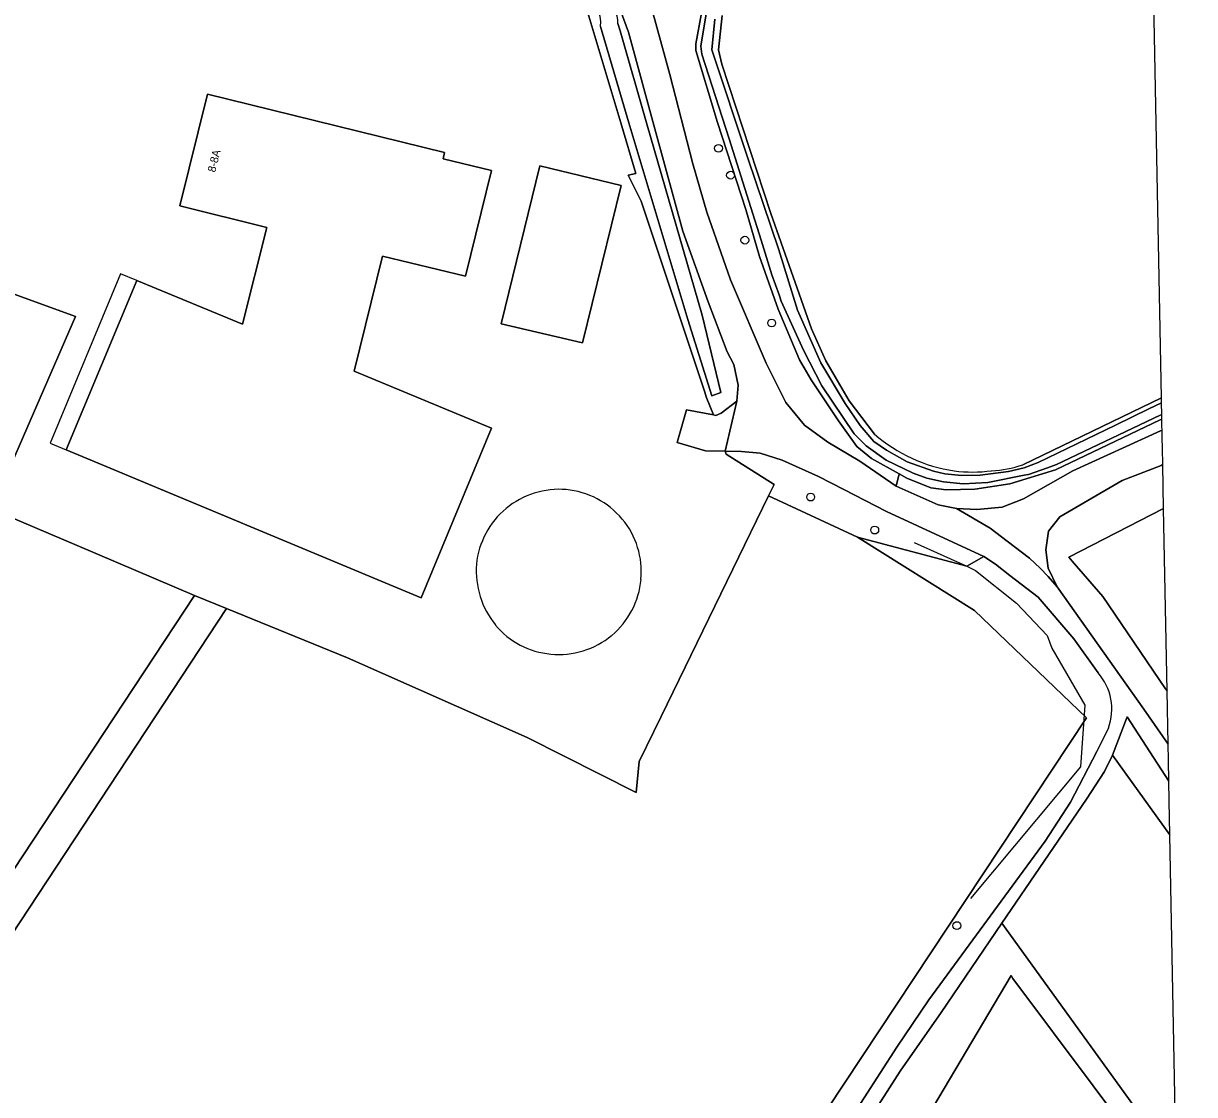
# Model space of a CAD drawing. Extents: x 163859 to 164644, y 379566 to 382155.
# Drawn here: x 164470.1 to 164616.4, y 381128.6 to 381262.4 of the extents above; entities that cross this region are included whole.
import ezdxf

# ---------------------------------------------------------------- set-up
doc = ezdxf.new("R2010")
doc.units = 0
for name, color, linetype in [('IMGEO_Berm_groen', 7, 'Continuous'), ('IMGEO_Boom', 7, 'Continuous'), ('IMGEO_Bouwland', 7, 'Continuous'), ('IMGEO_Erf', 7, 'Continuous'), ('IMGEO_Gemengd_bos', 7, 'Continuous'), ('IMGEO_Grasland_agrarisch', 7, 'Continuous'), ('IMGEO_Grasland_overig', 7, 'Continuous'), ('IMGEO_Groenvoorziening', 7, 'Continuous'), ('IMGEO_Hek', 7, 'Continuous'), ('IMGEO_Loofbos', 7, 'Continuous'), ('IMGEO_Oever', 7, 'Continuous'), ('IMGEO_Open_loods', 7, 'Continuous'), ('IMGEO_Pand', 7, 'Continuous'), ('IMGEO_Pand_nummerreeks', 7, 'Continuous'), ('IMGEO_Pand_overbouw', 7, 'Continuous'), ('IMGEO_Rijbaan_lokaal_onverhard', 7, 'Continuous'), ('IMGEO_Rijbaan_lokaal_open', 7, 'Continuous'), ('IMGEO_Sloot', 7, 'Continuous'), ('IMGEO_Waterloop', 7, 'Continuous')]:
    doc.layers.add(name, color=color, linetype=linetype)

msp = doc.modelspace()

# ---------------------------------------------------------------- linework, layer by layer
at = {"layer": 'IMGEO_Berm_groen'}
msp.add_lwpolyline([(164612.31, 381212.99), (164612.12, 381212.9), (164599.01, 381206.67), (164593.32, 381204.91), (164588.95, 381204.24), (164585.35, 381204.15), (164583.43, 381204.4), (164580.44, 381205.6), (164579.48, 381206.15), (164579.11, 381204.6), (164584.36, 381202.3), (164586.65, 381201.83), (164589.18, 381201.68), (164592.36, 381201.97), (164595.03, 381203.03), (164601.2, 381206.54), (164612.15, 381211.51), (164612.34, 381211.58), (164612.32, 381212.16)], close=True, dxfattribs=at)
msp.add_lwpolyline([(164612.52, 381201.83), (164612.42, 381207.28), (164612.42, 381207.3), (164612.23, 381207.21), (164607.37, 381205.34), (164602.57, 381202.55), (164599.56, 381200.8), (164598.14, 381198.98), (164597.81, 381196.68), (164598.11, 381194.37), (164599.24, 381192.03), (164610.08, 381176.78), (164613.09, 381172.4), (164612.96, 381179.03), (164612.77, 381179.3), (164604.93, 381190.83), (164601.11, 381195.25), (164600.71, 381195.76), (164612.52, 381201.83)], dxfattribs=at)
at = {"layer": 'IMGEO_Boom'}
for centre in [(164556.92, 381246.81), (164558.42, 381243.45), (164560.21, 381235.34), (164563.56, 381224.99), (164568.43, 381203.25), (164576.44, 381199.13), (164586.7, 381149.73)]:
    msp.add_circle(centre, 0.489, dxfattribs=at)
at = {"layer": 'IMGEO_Bouwland'}
msp.add_lwpolyline([(164616.41, 381000), (164614.83, 381082.01), (164614.18, 381115.76), (164613.76, 381116.31), (164593.71, 381143.13), (164593.47, 381143.48), (164578.88, 381118.83), (164571.39, 381110.35), (164562.91, 381102.27), (164557.19, 381097.73), (164551.27, 381095.96), (164545.16, 381095.56), (164539.05, 381095.96), (164528.79, 381097.14), (164521.89, 381098.72), (164511.44, 381102.66), (164434.34, 380973.7)], dxfattribs=at)
at = {"layer": 'IMGEO_Erf'}
for points in [[(164466.17, 381201.68), (164476.78, 381197.2), (164491.42, 381190.96), (164495.42, 381189.33), (164510.56, 381183.16), (164532.99, 381173.22), (164546.62, 381166.36), (164547, 381170.23), (164549.74, 381175.85), (164563.17, 381203.39), (164563.87, 381204.82), (164557.87, 381208.62), (164557.76, 381208.98), (164555.31, 381209.02), (164551.74, 381210.06), (164552.9, 381214.15), (164556.3, 381213.51), (164555.39, 381215.78), (164555.19, 381216.36), (164547.24, 381240.23), (164545.64, 381243.44), (164546.57, 381243.66), (164544.69, 381250), (164540.48, 381264.15)], [(164455.37, 381233.49), (164476.57, 381225.79), (164468.67, 381207.69)]]:
    msp.add_lwpolyline(points, dxfattribs=at)
for points in [[(164493.07, 381253.59), (164522.69, 381246.3), (164522.5, 381245.5), (164528.55, 381244.02), (164525.29, 381230.84), (164514.94, 381233.36), (164511.38, 381218.98), (164528.53, 381211.84), (164519.74, 381190.67), (164475.41, 381209.15), (164484.22, 381230.3), (164497.43, 381224.83), (164500.46, 381236.94), (164489.62, 381239.63)], [(164534.59, 381244.64), (164544.74, 381242.15), (164539.92, 381222.53), (164529.75, 381224.89)]]:
    msp.add_lwpolyline(points, close=True, dxfattribs=at)
for centre, radius, start, end in [((164537.02, 381193.77), 10.45, 85.2742, 129.4704), ((164536.91, 381193.84), 10.39, 39.9242, 84.6782), ((164537.04, 381193.81), 10.43, 129.7074, 174.2176), ((164537.07, 381193.95), 10.2, 354.472, 40.0119), ((164537.55, 381194.13), 10.92, 176.1353, 218.8855), ((164537, 381193.87), 10.27, 309.7584, 354.9208), ((164536.78, 381193.59), 9.98, 219.2706, 265.2458), ((164537, 381193.79), 10.2, 264.0995, 310.0286)]:
    msp.add_arc(centre, radius, start, end, dxfattribs=at)
at = {"layer": 'IMGEO_Gemengd_bos'}
for points in [[(164604.35, 381181.3), (164601.31, 381185.54), (164596.85, 381190.77), (164593.3, 381193.47), (164591.51, 381194.86), (164590.09, 381195.84), (164587.94, 381194.61), (164574.27, 381198.23), (164588.92, 381189.1), (164602.9, 381175.67), (164557.53, 381107.22)], [(164557.53, 381107.22), (164561.61, 381110.39), (164565.12, 381114.11), (164571.02, 381121.89), (164579.18, 381134.54), (164583.18, 381140.44), (164597.75, 381160.27), (164600.92, 381165.15), (164604.2, 381171.47), (164605.64, 381174.38)]]:
    msp.add_lwpolyline(points, dxfattribs=at)
msp.add_arc((164599.17, 381176.75), 6.89, 339.9252, 41.3342, dxfattribs=at)
at = {"layer": 'IMGEO_Grasland_agrarisch'}
for points in [[(164612.26, 381215.65), (164611.6, 381250), (164610.02, 381332.03)], [(164557.37, 381263.39), (164556.93, 381259.1), (164557.34, 381257.3), (164563.46, 381238.67), (164568.53, 381224.27), (164570.32, 381220.27), (164573.23, 381215.26), (164576.41, 381211.1)], [(164394.38, 381043.92), (164491.42, 381190.96), (164476.78, 381197.2), (164466.17, 381201.68), (164468.67, 381207.69), (164476.57, 381225.79), (164455.37, 381233.49), (164449.22, 381234.75), (164447.64, 381227.22), (164435.91, 381232.23)], [(164594.95, 381207.29), (164612.26, 381215.65)], [(164557.53, 381107.22), (164602.9, 381175.67), (164588.92, 381189.1), (164574.27, 381198.23), (164563.17, 381203.39), (164549.74, 381175.85), (164547, 381170.23), (164546.62, 381166.36), (164532.99, 381173.22), (164510.56, 381183.16), (164495.42, 381189.33), (164397.81, 381041.2)]]:
    msp.add_lwpolyline(points, dxfattribs=at)
for points in [[(164612.96, 381179.03), (164612.52, 381201.83), (164600.71, 381195.76), (164601.11, 381195.25), (164604.93, 381190.83), (164612.77, 381179.3)], [(164613.31, 381161.07), (164606.14, 381171.03), (164605.16, 381168.97), (164602.88, 381165.5), (164592.33, 381150.04), (164614.1, 381119.89)]]:
    msp.add_lwpolyline(points, close=True, dxfattribs=at)
for centre, radius, start, end in [((164589.43, 381226.31), 20.03, 229.4578, 261.2234), ((164588.66, 381224.46), 18.08, 262.7499, 277.4727), ((164590.23, 381221.16), 14.65, 273.04, 288.814)]:
    msp.add_arc(centre, radius, start, end, dxfattribs=at)
at = {"layer": 'IMGEO_Grasland_overig'}
msp.add_lwpolyline([(164495.42, 381189.33), (164491.42, 381190.96), (164394.38, 381043.92), (164397.81, 381041.2)], close=True, dxfattribs=at)
at = {"layer": 'IMGEO_Groenvoorziening'}
for points in [[(164549.08, 381248.8), (164545.66, 381261.33), (164544.34, 381264.96), (164543.02, 381266.93), (164541.43, 381268.75), (164538.66, 381270.43), (164529.34, 381273.18), (164519.5, 381276.01), (164498.67, 381282.49), (164483.96, 381287.46), (164474.21, 381290.55), (164474.18, 381290.13), (164473.36, 381289.22), (164473.39, 381289.21), (164474.43, 381290.12), (164482.88, 381287.29)], [(164547.6, 381267.91), (164550.85, 381256.01), (164553.72, 381244.89), (164555.47, 381238.84), (164558.43, 381230.39), (164562.87, 381219.96), (164565.32, 381215.07), (164567.68, 381212.22), (164570.59, 381210.11), (164574.56, 381207.73), (164579.11, 381204.6), (164579.48, 381206.15), (164576.04, 381208.08), (164574.18, 381209.58), (164571.91, 381212.76), (164568.5, 381217.9), (164567.04, 381220.38), (164564.38, 381226.73), (164562.03, 381233.31), (164560.31, 381239.18), (164556.78, 381250.03), (164554.07, 381259.03), (164554.09, 381259.85), (164554.8, 381263.71)], [(164540.48, 381264.15), (164544.69, 381250), (164546.57, 381243.66), (164545.64, 381243.44), (164547.24, 381240.23), (164555.19, 381216.36), (164555.39, 381215.78), (164556.3, 381213.51), (164556.58, 381213.46), (164557.24, 381213.71), (164559.22, 381215.24), (164559.36, 381217.23), (164558.81, 381219.82), (164557.99, 381221.41), (164555.63, 381227.65), (164552.47, 381236.46), (164549.08, 381248.8)], [(164544.35, 381262.41), (164544.61, 381261.49), (164547.93, 381250), (164554.87, 381225.96), (164557.19, 381216.3), (164556.08, 381215.89), (164553.07, 381225.44), (164545.72, 381250)], [(164545.72, 381250), (164542.18, 381262.02)]]:
    msp.add_lwpolyline(points, dxfattribs=at)
msp.add_lwpolyline([(164557.76, 381208.98), (164557.87, 381208.62), (164563.87, 381204.82), (164563.17, 381203.39), (164574.27, 381198.23), (164587.94, 381194.61), (164590.09, 381195.84), (164577.91, 381201.43), (164572.58, 381204.2), (164569.39, 381205.84), (164564.89, 381207.88), (164562.14, 381208.75), (164559.78, 381208.94)], close=True, dxfattribs=at)
for centre, radius, start, end in [((164538.44, 381262.22), 5.91, 1.8256, 71.6465), ((164538.88, 381262.54), 3.34, 350.9797, 76.274)]:
    msp.add_arc(centre, radius, start, end, dxfattribs=at)
at = {"layer": 'IMGEO_Hek'}
for points in [[(164546.57, 381243.66), (164545.64, 381243.44), (164547.24, 381240.23)], [(164468.67, 381207.69), (164476.57, 381225.79), (164455.37, 381233.49), (164449.22, 381234.75)], [(164491.42, 381190.96), (164476.78, 381197.2), (164466.17, 381201.68), (164468.67, 381207.69)], [(164547, 381170.23), (164549.74, 381175.85), (164563.87, 381204.82)], [(164581.36, 381197.59), (164587.94, 381194.61)], [(164587.94, 381194.61), (164588.1, 381194.54)], [(164588.1, 381194.54), (164589.05, 381194.1), (164594.17, 381190.01), (164597.98, 381185.97), (164598.57, 381184.37), (164602.69, 381177.28), (164602.15, 381169.55), (164588.41, 381153.12)], [(164495.42, 381189.33), (164397.81, 381041.2), (164394.38, 381043.92), (164491.42, 381190.96)], [(164491.42, 381190.96), (164495.42, 381189.33)], [(164495.42, 381189.33), (164510.56, 381183.16), (164532.99, 381173.22), (164546.62, 381166.36)]]:
    msp.add_lwpolyline(points, dxfattribs=at)
at = {"layer": 'IMGEO_Loofbos'}
for points in [[(164613.31, 381161.07), (164613.23, 381165.33), (164613.18, 381167.75), (164607.99, 381175.81), (164606.14, 381171.03), (164613.31, 381161.07)], [(164614.1, 381119.89), (164592.33, 381150.04), (164584.73, 381138.89), (164579.6, 381131.54), (164575.89, 381125.77)], [(164578.88, 381118.83), (164593.47, 381143.48), (164593.71, 381143.13), (164613.76, 381116.31)]]:
    msp.add_lwpolyline(points, dxfattribs=at)
at = {"layer": 'IMGEO_Oever'}
for points in [[(164554.8, 381263.71), (164554.09, 381259.85), (164554.07, 381259.03), (164556.78, 381250.03), (164560.31, 381239.18), (164562.03, 381233.31), (164564.38, 381226.73), (164567.04, 381220.38), (164568.5, 381217.9), (164571.91, 381212.76), (164574.18, 381209.58), (164576.04, 381208.08), (164579.48, 381206.15), (164580.44, 381205.6), (164583.43, 381204.4), (164585.35, 381204.15), (164588.95, 381204.24), (164593.32, 381204.91), (164599.01, 381206.67), (164612.12, 381212.9), (164612.31, 381212.99)], [(164612.31, 381212.99), (164612.3, 381213.51), (164612.3, 381213.56), (164612.11, 381213.48), (164599.14, 381207.33), (164598.04, 381206.92), (164595.65, 381206.09), (164595.1, 381205.99), (164590.58, 381205.08), (164587.47, 381204.89), (164585.04, 381205.16), (164582.94, 381205.6), (164581.23, 381206.22), (164577.88, 381207.87), (164575.36, 381209.65), (164573.86, 381211.15), (164569.82, 381217.16), (164567.53, 381221.61), (164564.76, 381227.74), (164564.48, 381228.53), (164563.59, 381231.01), (164562.23, 381235.35), (164560.95, 381239.43), (164558.24, 381248), (164554.85, 381258.56), (164554.72, 381259.58), (164555.36, 381263.6)], [(164556.47, 381262.94), (164556.08, 381259.13), (164560.56, 381245.59), (164564.44, 381234.15), (164566.79, 381226.61), (164569.72, 381220.02), (164572.74, 381214.93), (164574.61, 381212.18), (164576.33, 381210.2), (164577.91, 381209.11), (164580.5, 381207.67), (164583.79, 381206.47), (164585.2, 381206.16), (164587.3, 381205.94), (164589.63, 381205.99), (164593.16, 381206.43), (164595.11, 381206.92), (164596.87, 381207.55), (164606.54, 381212.23), (164610.67, 381214.26), (164612.27, 381215.01), (164612.26, 381215.65), (164594.95, 381207.29)], [(164576.41, 381211.1), (164573.23, 381215.26), (164570.32, 381220.27), (164568.53, 381224.27), (164563.46, 381238.67), (164557.34, 381257.3), (164556.93, 381259.1), (164557.37, 381263.39)]]:
    msp.add_lwpolyline(points, dxfattribs=at)
for centre, radius, start, end in [((164589.43, 381226.31), 20.03, 229.4578, 261.2234), ((164588.66, 381224.46), 18.08, 262.7499, 277.4727), ((164590.23, 381221.16), 14.65, 273.04, 288.814)]:
    msp.add_arc(centre, radius, start, end, dxfattribs=at)
at = {"layer": 'IMGEO_Open_loods'}
for centre, radius, start, end in [((164537.02, 381193.77), 10.45, 85.2742, 129.4704), ((164536.91, 381193.84), 10.39, 39.9242, 84.6782), ((164537.04, 381193.81), 10.43, 129.7074, 174.2176), ((164537.07, 381193.95), 10.2, 354.472, 40.0119), ((164537.55, 381194.13), 10.92, 176.1353, 218.8855), ((164537, 381193.87), 10.27, 309.7584, 354.9208), ((164536.78, 381193.59), 9.98, 219.2706, 265.2458), ((164537, 381193.79), 10.2, 264.0995, 310.0286)]:
    msp.add_arc(centre, radius, start, end, dxfattribs=at)
at = {"layer": 'IMGEO_Pand'}
for points in [[(164514.94, 381233.36), (164525.29, 381230.84), (164528.55, 381244.02), (164522.5, 381245.5), (164522.69, 381246.3), (164493.07, 381253.59), (164489.62, 381239.63), (164500.46, 381236.94), (164497.43, 381224.83), (164484.22, 381230.3), (164475.41, 381209.15), (164519.74, 381190.67), (164528.53, 381211.84), (164511.38, 381218.98)], [(164539.92, 381222.53), (164544.74, 381242.15), (164534.59, 381244.64), (164529.75, 381224.89)]]:
    msp.add_lwpolyline(points, close=True, dxfattribs=at)
at = {"layer": 'IMGEO_Pand_overbouw'}
msp.add_lwpolyline([(164484.22, 381230.3), (164482.19, 381231.14), (164473.38, 381210), (164475.41, 381209.15)], close=True, dxfattribs=at)
at = {"layer": 'IMGEO_Rijbaan_lokaal_onverhard'}
for points in [[(164613.09, 381172.4), (164610.08, 381176.78), (164599.24, 381192.03), (164598.13, 381193.31), (164597.11, 381194.38), (164595.79, 381195.61), (164593, 381197.74), (164590.86, 381199.36), (164586.65, 381201.83), (164584.36, 381202.3), (164579.11, 381204.6), (164574.56, 381207.73), (164570.59, 381210.11), (164567.68, 381212.22), (164565.32, 381215.07), (164562.87, 381219.96), (164558.43, 381230.39), (164555.47, 381238.84), (164553.72, 381244.89), (164550.85, 381256.01), (164547.6, 381267.91), (164544.02, 381275.23), (164536.24, 381278.12)], [(164544.34, 381264.96), (164545.66, 381261.33), (164549.08, 381248.8), (164552.47, 381236.46), (164555.63, 381227.65), (164557.99, 381221.41), (164558.81, 381219.82), (164559.36, 381217.23), (164559.22, 381215.24), (164557.76, 381208.98), (164559.78, 381208.94), (164562.14, 381208.75), (164564.89, 381207.88), (164569.39, 381205.84), (164572.58, 381204.2), (164577.91, 381201.43), (164590.09, 381195.84), (164591.51, 381194.86), (164593.3, 381193.47), (164596.85, 381190.77), (164601.31, 381185.54), (164604.35, 381181.3)], [(164612.34, 381211.58), (164612.15, 381211.51), (164601.2, 381206.54), (164595.03, 381203.03), (164592.36, 381201.97), (164589.18, 381201.68), (164586.65, 381201.83), (164590.86, 381199.36), (164593, 381197.74), (164595.79, 381195.61), (164597.11, 381194.38), (164598.13, 381193.31), (164599.24, 381192.03), (164598.11, 381194.37), (164597.81, 381196.68), (164598.14, 381198.98), (164599.56, 381200.8), (164602.57, 381202.55), (164607.37, 381205.34), (164612.23, 381207.21), (164612.42, 381207.3), (164612.38, 381209.32), (164612.35, 381210.7), (164612.34, 381211.58)], [(164509.94, 381110.46), (164513, 381109.56), (164528.45, 381102.23), (164535.88, 381100.11), (164539.67, 381099.67), (164543.21, 381099.75), (164547.64, 381100.28), (164552.22, 381101.59), (164557.08, 381104.16), (164561.26, 381107.19), (164565.4, 381111.59), (164572.27, 381120.6), (164575.89, 381125.77), (164579.6, 381131.54), (164584.73, 381138.89), (164592.33, 381150.04), (164602.88, 381165.5), (164605.16, 381168.97), (164606.14, 381171.03), (164607.99, 381175.81), (164613.18, 381167.75), (164613.13, 381170.4), (164613.09, 381172.4)], [(164605.64, 381174.38), (164604.2, 381171.47), (164600.92, 381165.15), (164597.75, 381160.27), (164583.18, 381140.44), (164579.18, 381134.54), (164571.02, 381121.89), (164565.12, 381114.11), (164561.61, 381110.39), (164557.53, 381107.22), (164555.31, 381105.49), (164553.14, 381104.2), (164550.89, 381103.22), (164547.61, 381102.5), (164541.67, 381102), (164537.77, 381102.28), (164531.66, 381103.46), (164528.71, 381104.56), (164514.89, 381111.01), (164511.96, 381112.11)]]:
    msp.add_lwpolyline(points, dxfattribs=at)
msp.add_arc((164599.17, 381176.75), 6.89, 339.9252, 41.3342, dxfattribs=at)
at = {"layer": 'IMGEO_Rijbaan_lokaal_open'}
msp.add_lwpolyline([(164559.22, 381215.24), (164557.24, 381213.71), (164556.58, 381213.46), (164556.3, 381213.51), (164552.9, 381214.15), (164551.74, 381210.06), (164555.31, 381209.02), (164557.76, 381208.98)], close=True, dxfattribs=at)
at = {"layer": 'IMGEO_Sloot'}
msp.add_lwpolyline([(164555.36, 381263.6), (164554.72, 381259.58), (164554.85, 381258.56), (164558.24, 381248), (164560.95, 381239.43), (164562.23, 381235.35), (164563.59, 381231.01), (164564.48, 381228.53), (164564.76, 381227.74), (164567.53, 381221.61), (164569.82, 381217.16), (164573.86, 381211.15), (164575.36, 381209.65), (164577.88, 381207.87), (164581.23, 381206.22), (164582.94, 381205.6), (164585.04, 381205.16), (164587.47, 381204.89), (164590.58, 381205.08), (164595.1, 381205.99), (164595.65, 381206.09), (164598.04, 381206.92), (164599.14, 381207.33), (164612.11, 381213.48), (164612.3, 381213.56), (164612.27, 381215.01), (164610.67, 381214.26), (164606.54, 381212.23), (164596.87, 381207.55), (164595.11, 381206.92), (164593.16, 381206.43), (164589.63, 381205.99), (164587.3, 381205.94), (164585.2, 381206.16), (164583.79, 381206.47), (164580.5, 381207.67), (164577.91, 381209.11), (164576.33, 381210.2), (164574.61, 381212.18), (164572.74, 381214.93), (164569.72, 381220.02), (164566.79, 381226.61), (164564.44, 381234.15), (164560.56, 381245.59), (164556.08, 381259.13), (164556.47, 381262.94)], dxfattribs=at)
at = {"layer": 'IMGEO_Waterloop'}
msp.add_lwpolyline([(164542.18, 381262.02), (164545.72, 381250), (164553.07, 381225.44), (164556.08, 381215.89), (164557.19, 381216.3), (164554.87, 381225.96), (164547.93, 381250), (164544.61, 381261.49), (164544.35, 381262.41)], dxfattribs=at)
for centre, radius, start, end in [((164538.44, 381262.22), 5.91, 1.8256, 71.6465), ((164538.88, 381262.54), 3.34, 350.9797, 76.274)]:
    msp.add_arc(centre, radius, start, end, dxfattribs=at)

# ---------------------------------------------------------------- texts
at = {"layer": 'IMGEO_Pand_nummerreeks'}
msp.add_text('8-8A', height=1, rotation=75.8883, dxfattribs=at).set_placement((164494.02, 381243.75))

doc.saveas('drawing.dxf')
